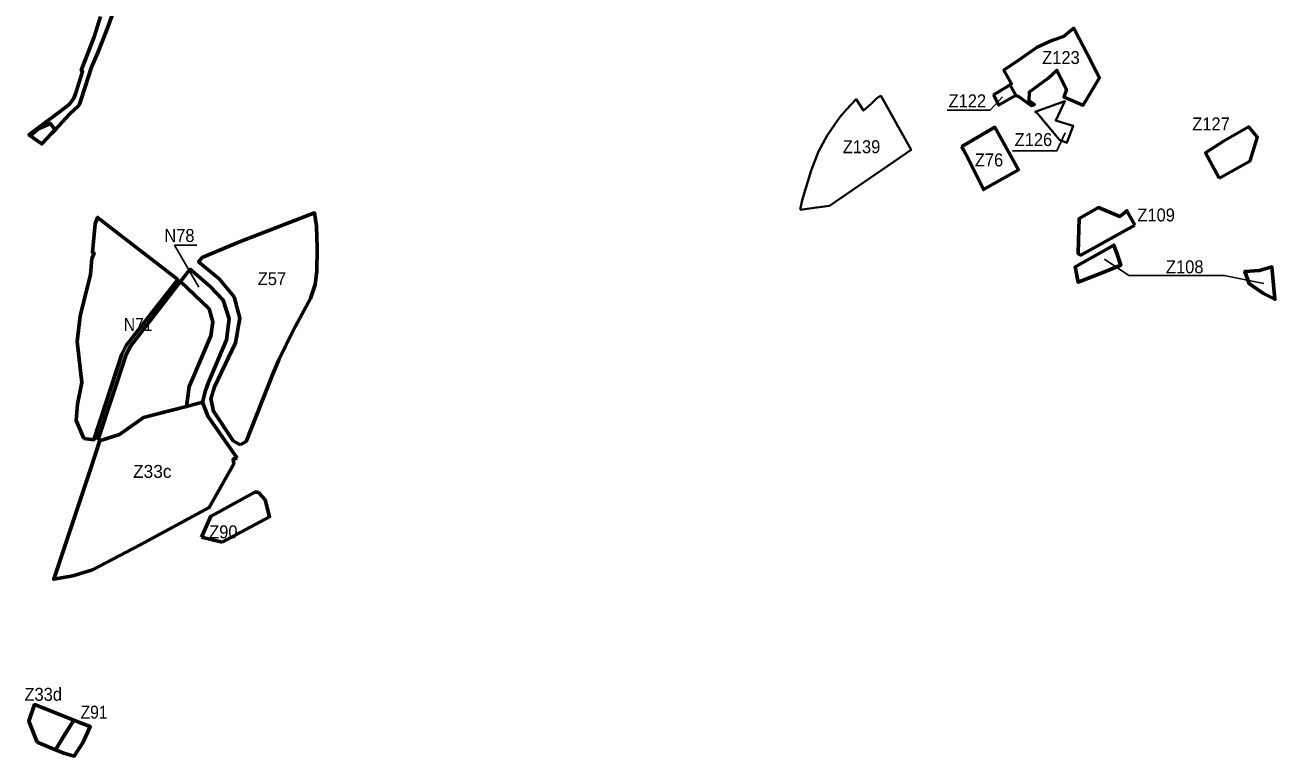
# Model space of a CAD drawing. Extents: x -650277 to -643422, y -1073980 to -1066720.
# Drawn here: x -648572 to -646257, y -1073980 to -1072626 of the extents above; entities that cross this region are included whole.
import ezdxf

# ---------------------------------------------------------------- set-up
doc = ezdxf.new("R2010")
doc.units = 0
doc.header["$LTSCALE"] = 9.6
for name, color, linetype, lineweight in [('1', 7, 'Continuous', 60), ('18', 7, 'Continuous', 60), ('2', 7, 'Continuous', 40), ('24', 7, 'Continuous', 60), ('34', 7, 'Continuous', 60), ('35', 7, 'Continuous', 60), ('45', 7, 'Continuous', 60), ('48', 7, 'Continuous', 60), ('5', 7, 'Continuous', 60), ('59', 7, 'Continuous', 25), ('60', 7, 'Continuous', 60), ('63', 7, 'Continuous', 25), ('9', 7, 'Continuous', 60)]:
    doc.layers.add(name, color=color, linetype=linetype, lineweight=lineweight)

msp = doc.modelspace()

# ---------------------------------------------------------------- linework, layer by layer
at = {"layer": '1', "lineweight": 53}
for points in [[(-646737.05, -1072756.4), (-646732.5, -1072757.63), (-646708.65, -1072775.02), (-646702.45, -1072773.39), (-646712.46, -1072766.76), (-646711.79, -1072750.02), (-646677.39, -1072724.85), (-646660.89, -1072709.97), (-646643.36, -1072746.04), (-646647.93, -1072759.01), (-646612.11, -1072774.56), (-646581.92, -1072723.91), (-646589.37, -1072709.83), (-646605.23, -1072679.37), (-646627.32, -1072636.95), (-646629.86, -1072632.07), (-646648.27, -1072647.48), (-646669.6, -1072654.53), (-646697.89, -1072667.65)], [(-646697.89, -1072667.65), (-646732.95, -1072691.68), (-646759.491, -1072709.878), (-646757.5, -1072713.3), (-646747.87, -1072729.85), (-646744.94, -1072734.88), (-646748.3, -1072737.01), (-646737.05, -1072756.4)]]:
    msp.add_lwpolyline(points, dxfattribs=at)
for points in [[(-646778.2, -1072755.19), (-646755.1, -1072741.28), (-646748.3, -1072737.01), (-646737.05, -1072756.4), (-646768.74, -1072774.78)], [(-646360.22, -1072909.57), (-646303.02, -1072877.74), (-646289.63, -1072834.04), (-646305.56, -1072814.43), (-646353.25, -1072841.63), (-646385.86, -1072862.59)]]:
    msp.add_lwpolyline(points, close=True, dxfattribs=at)
at = {"layer": '1', "lineweight": 25}
msp.add_lwpolyline([(-646864.278, -1072783.783), (-646784.878, -1072783.783), (-646761.687, -1072759.411)], dxfattribs=at)
at = {"layer": '1', "lineweight": 40}
for points in [[(-646653.02, -1072806.07), (-646663.07, -1072803.04), (-646663.07, -1072803.04), (-646646.12, -1072767.32), (-646646.31, -1072767.388), (-646701.12, -1072787.08), (-646697.09, -1072790.03), (-646656.36, -1072839.08)], [(-646656.36, -1072839.08), (-646642.404, -1072844.195), (-646631.08, -1072812.68), (-646643.01, -1072809.08), (-646651.11, -1072806.64), (-646653.02, -1072806.07)]]:
    msp.add_lwpolyline(points, dxfattribs=at)
at = {"layer": '18'}
msp.add_lwpolyline([(-646837.81, -1072851.3), (-646836.5, -1072853.76), (-646833.67, -1072857.15), (-646824.89, -1072874.66), (-646796.68, -1072930.92), (-646732.28, -1072894.29), (-646775.85, -1072815.39), (-646834.08, -1072849.15)], close=True, dxfattribs=at)
at = {"layer": '2'}
for points in [[(-646987.154, -1072756.377), (-646995.02, -1072762.45), (-647005.249, -1072771.938), (-647019.06, -1072784.57), (-647032.7, -1072763.68), (-647050.492, -1072782.771)], [(-646954.7, -1072815.232), (-646957.105, -1072810.92), (-646987.154, -1072756.377)], [(-647050.492, -1072782.771), (-647063.04, -1072796.74), (-647067.22, -1072802.77), (-647086.65, -1072830.76), (-647102.38, -1072860.7), (-647116.33, -1072895.3)], [(-647136.39, -1072968.63), (-647110.32, -1072964.56), (-647107.01, -1072964.04), (-647105.4, -1072963.84), (-647082.36, -1072960.95), (-646931.1, -1072857.55), (-646954.51, -1072815.63), (-646954.7, -1072815.232)], [(-647116.33, -1072895.3), (-647132.47, -1072950.4), (-647136.39, -1072968.63)]]:
    msp.add_lwpolyline(points, dxfattribs=at)
at = {"layer": '24'}
for points in [[(-648524.04, -1072809.71), (-648525.08, -1072808.24), (-648547.06, -1072818.59), (-648561.69, -1072831.54), (-648554.22, -1072836.89), (-648541.102, -1072846.281), (-648522.66, -1072826.92), (-648516.44, -1072820.39)], [(-648549.76, -1073954.86), (-648515.333, -1073968.584), (-648498, -1073940), (-648481.749, -1073913.76), (-648554.42, -1073885.092), (-648564.75, -1073915.91)]]:
    msp.add_lwpolyline(points, close=True, dxfattribs=at)
at = {"layer": '34'}
for points in [[(-646574.156, -1073083.691), (-646542.62, -1073071.1), (-646550.01, -1073048.55), (-646552.79, -1073041.53), (-646555.79, -1073033.92), (-646624.69, -1073072.66), (-646626.967, -1073073.918), (-646621.38, -1073102.66), (-646620.19, -1073102.14), (-646618.56, -1073101.42)], [(-646298.029, -1073109.723), (-646278.38, -1073123.25), (-646257.09, -1073134.01), (-646262.94, -1073074.15), (-646285.77, -1073081.01), (-646312.87, -1073082.4), (-646305.18, -1073104.8)]]:
    msp.add_lwpolyline(points, close=True, dxfattribs=at)
at = {"layer": '35'}
msp.add_lwpolyline([(-646516.7, -1072996.65), (-646531.46, -1072970.12), (-646544.68, -1072980.62), (-646584.23, -1072964.22), (-646619.48, -1072984.34), (-646620.71, -1073025.49), (-646621.44, -1073049.79), (-646616.55, -1073052.21)], close=True, dxfattribs=at)
at = {"layer": '45'}
for points in [[(-648463.25, -1073392.125), (-648444.523, -1073394.235), (-648392.43, -1073235.98), (-648384.6, -1073219.54), (-648315.955, -1073131.889), (-648289.148, -1073097.66), (-648437.643, -1072982.601), (-648442.187, -1072994.5), (-648447.043, -1073046.967), (-648444.11, -1073048.69), (-648448.1, -1073058.393)], [(-648448.1, -1073058.393), (-648450.875, -1073088.375), (-648469.875, -1073165.5), (-648475.437, -1073212.375), (-648466.687, -1073288.25), (-648474.5, -1073328.75), (-648477.562, -1073358.875), (-648463.25, -1073392.125)], [(-648272.642, -1073332.558), (-648268, -1073296), (-648261, -1073280), (-648228, -1073202), (-648224, -1073176), (-648231, -1073152), (-648283.884, -1073101.15), (-648311.798, -1073137.127), (-648378.17, -1073222.67), (-648385.09, -1073238.58), (-648436.857, -1073395.099)], [(-648397.062, -1073384.375), (-648378.125, -1073370.875), (-648352.312, -1073353), (-648314.687, -1073343.25), (-648272.642, -1073332.558)], [(-648436.857, -1073395.099), (-648432.187, -1073395.625), (-648397.062, -1073384.375)]]:
    msp.add_lwpolyline(points, dxfattribs=at)
at = {"layer": '48'}
msp.add_lwpolyline([(-648231, -1073152), (-648224, -1073176), (-648228, -1073202), (-648261, -1073280), (-648268, -1073296), (-648272.642, -1073332.558), (-648243.08, -1073325.04), (-648237.98, -1073303.4), (-648232.64, -1073289.31), (-648198.7, -1073209.08), (-648194.2, -1073170.13), (-648205.04, -1073136.07), (-648228.91, -1073110.54), (-648266.38, -1073078.59), (-648283.884, -1073101.15)], close=True, dxfattribs=at)
at = {"layer": '5'}
for points in [[(-648272.642, -1073332.558), (-648352.312, -1073353), (-648397.062, -1073384.375)], [(-648179.07, -1073428.81), (-648233.36, -1073350.68), (-648243.08, -1073325.04), (-648272.642, -1073332.558)], [(-648397.062, -1073384.375), (-648432.187, -1073395.625), (-648433.206, -1073395.51), (-648449.599, -1073445.278)], [(-648447.06, -1073635.39), (-648358.69, -1073589.35), (-648230.81, -1073520.18), (-648185.34, -1073438.91), (-648185.82, -1073435.12), (-648186.46, -1073430.01), (-648183.46, -1073429.52), (-648179.07, -1073428.81)], [(-648449.599, -1073445.278), (-648518.867, -1073652.836), (-648483.58, -1073646.7), (-648447.06, -1073635.39), (-648447.06, -1073635.39)]]:
    msp.add_lwpolyline(points, dxfattribs=at)
at = {"layer": '60'}
msp.add_line((-648245.341, -1073575.152), (-648207, -1073584), dxfattribs=at)
for points in [[(-648432.45, -1072610.56), (-648443.77, -1072648.02), (-648468.01, -1072710.44), (-648465.25, -1072712.03), (-648478.58, -1072753.49), (-648481.62, -1072761.39), (-648489.76, -1072772.74), (-648506.1, -1072785.56), (-648542.43, -1072812.6), (-648564.86, -1072829.45), (-648561.69, -1072831.54), (-648547.06, -1072818.59), (-648525.08, -1072808.24), (-648524.04, -1072809.71), (-648516.44, -1072820.39), (-648489.69, -1072791.37), (-648473.13, -1072775.58), (-648470.89, -1072772.42), (-648467.286, -1072761.426), (-648448.58, -1072704.37), (-648436.75, -1072675.79), (-648418.45, -1072629.91), (-648409.08, -1072604.25)], [(-648139.56, -1073491.4), (-648146.4, -1073491.55), (-648220.42, -1073532.43), (-648227.63, -1073535.89), (-648245.341, -1073575.152)], [(-648207, -1073584), (-648119, -1073537), (-648127.31, -1073505.75), (-648138.41, -1073493.62), (-648139.56, -1073491.4)]]:
    msp.add_lwpolyline(points, dxfattribs=at)
msp.add_lwpolyline([(-648515.333, -1073968.584), (-648499.84, -1073974.76), (-648480.86, -1073980.25), (-648464.44, -1073954.69), (-648451.05, -1073925.87), (-648471, -1073918), (-648481.749, -1073913.76)], close=True, dxfattribs=at)
at = {"layer": '63'}
for points in [[(-646743, -1072859), (-646661, -1072859), (-646646, -1072826)], [(-648254, -1073034), (-648295, -1073034), (-648250, -1073112)], [(-646573, -1073060), (-646528, -1073090), (-646351, -1073090), (-646278, -1073105)]]:
    msp.add_lwpolyline(points, dxfattribs=at)
at = {"layer": '9'}
for points in [[(-648030.86, -1073039.71), (-648032.09, -1072998.65), (-648035.592, -1072974.222), (-648175.061, -1073027.551), (-648244.214, -1073056.657), (-648250.491, -1073064.698), (-648212.22, -1073096.39), (-648184.37, -1073129.89)], [(-648101.67, -1073246.63), (-648075.34, -1073191.93), (-648043.29, -1073132.97), (-648034.43, -1073107.07), (-648031.8, -1073082.07), (-648030.86, -1073039.71)], [(-648184.37, -1073129.89), (-648174.03, -1073168.94), (-648182.12, -1073214.56), (-648221.39, -1073296.24), (-648227.75, -1073318.75), (-648223.03, -1073341.59), (-648186.47, -1073396.47), (-648173.38, -1073404.03)], [(-648173.38, -1073404.03), (-648162.55, -1073397.4), (-648112.36, -1073270.87), (-648101.67, -1073246.63)]]:
    msp.add_lwpolyline(points, dxfattribs=at)

# ---------------------------------------------------------------- texts
at = {"layer": '59', "width": 0.95}
msp.add_text('Z139', height=24, dxfattribs=at).set_placement((-647057.605, -1072863.534))
at = {"layer": '63'}
for s, width, p in [('Z123', 0.95, (-646688.261, -1072698.34)), ('Z122', 0.95, (-646861.605, -1072778.534)), ('Z127', 0.95, (-646410.261, -1072821.34)), ('Z126', 0.95, (-646739.261, -1072850.34)), ('Z76', 0.95, (-646813, -1072888)), ('Z109', 0.95, (-646512, -1072990)), ('N78', 0.95, (-648314, -1073028)), ('Z108', 0.95, (-646459, -1073086)), ('Z57', 0.95, (-648141, -1073108)), ('N71', 0.9, (-648389, -1073193)), ('Z90', 0.95, (-648231, -1073577)), ('Z33d', 0.95, (-648573, -1073878)), ('Z91', 0.9, (-648469, -1073911))]:
    msp.add_text(s, height=24, dxfattribs=dict(at, width=width)).set_placement(p)
msp.add_text('Z33c', height=24, dxfattribs=at).set_placement((-648372, -1073465))

doc.saveas('drawing.dxf')
